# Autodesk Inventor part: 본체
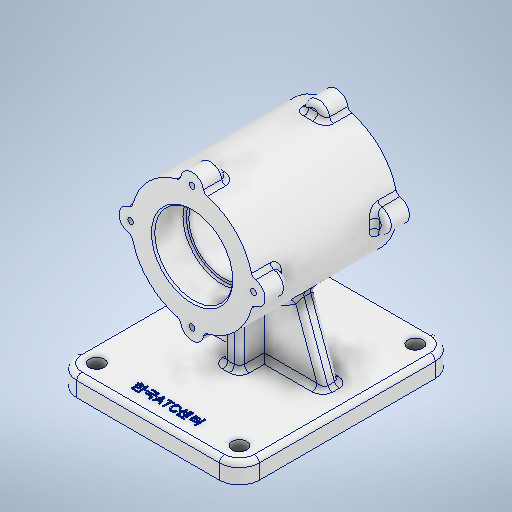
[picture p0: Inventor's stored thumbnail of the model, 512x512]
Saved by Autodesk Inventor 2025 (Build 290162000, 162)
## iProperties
Created: 2024-08
Part Number: 본체
Material: 알루미늄 6061
Document SubType Name: Modeling
Designer: Administrator
Density: 2.7 g/cm^3
Appearance: 알루미늄 - 평지
Mass: 1214.48 g
Surface Area: 799.178 cm^2
Volume: 449.808 cm^3
Author: Administrator
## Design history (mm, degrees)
sketch "스케치3"
  geometry: L1 (55, 70)-(-55, 70); L2 (-55, 70)-(-55, -60); L3 (-55, -60)-(55, -60); L4 (55, -60)-(55, 70); 1 further point
  constraints: 8 end point, 2 parallel, 1 horizontal, 1 perpendicular
  dimensions: "d7" = 70 distance from line of L1 point (0, 0); "d8" = 130 distance of L3.end L1.start; "d9" = 110 distance of L2.end L3.end; "d10" = 55 distance from line of L4 point (0, 0)
extrude "돌출2" new body sketch "스케치3" distance "d11" = 12; taper "d12" = 0 deg
sketch "스케치4"
  geometry: C1 r 37 at (0, 82); 1 further point
  constraints: 1 centre point, 1 vertical alignment
  dimensions: "d13" = 82 distance of point (0, 0) C1.centre; "d15" = 37 radius of C1
extrude "돌출3" join sketch "스케치4" stored distance "d16" = 87; taper "d17" = 0 deg
fillet "모깎기1" dims "d18" = 12
sketch "스케치5"
  geometry: L1 (43, 12)-(-43, 12) reference; L2 (-55, 12)-(-43, 12) reference; L3 (43, 12)-(55, 12) reference; L4 (41, 12)-(13.165, 88.475); L5 (-41, 12)-(-13.165, 88.475); L6 (-13.165, 88.475)-(13.165, 88.475); 2 further points
  constraints: 6 end point, 2 point on line, 1 equal length
  dimensions: "d20" = 14 distance of L3.end L4.start; "d21" = 110 deg angle of L3 L4; "d22" = 14 distance of L2.start L5.start; "d23" = 110 deg angle of L2 L5
extrude "돌출4" join sketch "스케치5" stored distance "d24" = 10; taper "d25" = 0 deg
sketch "스케치6"
  geometry: L1 (-5, -20)-(5, -20); L2 (5, -20)-(5, 20); L3 (5, 20)-(-5, 20); L4 (-5, 20)-(-5, -20); L5 (-5, -20)-(5, 20); L6 (5, -20)-(-5, 20); 1 further point
  constraints: 12 end point, 2 midpoint, 2 parallel, 1 horizontal, 1 perpendicular
  dimensions: "d26" = 40 distance of L3.end L1.start; "d27" = 10 distance of L2.end L3.end
extrude "돌출5" join sketch "스케치6" distance "d28" = 70; taper "d29" = 0 deg
sketch "스케치7"
  geometry: C1 r 37 at (0, 0) reference; 2 further points
  constraints: 1 coincident
hole "구멍1" sketch "스케치7" at (0, 0) diameter "d30" = 47; stored, may be unused: countersink angle "d34" = 90 deg, drill point angle "d36" = 0 deg; dims "d31" = 6, "d32" = 4, "d33" = 2, "d35" = 19
sketch "스케치8"
  geometry: C1 r 23.5 at (0, 0) reference; 2 further points
  constraints: 1 coincident
hole "구멍2" sketch "스케치8" at (0, 0) diameter "d37" = 42; stored, may be unused: countersink angle "d41" = 90 deg, drill point angle "d43" = 0 deg; dims "d38" = 6, "d39" = 4, "d40" = 2, "d42" = 1000
sketch "스케치9"
  geometry: C1 r 37 at (0, 0) reference; 2 further points
  constraints: 1 coincident
hole "구멍3" sketch "스케치9" at (0, 0) diameter "d44" = 47; stored, may be unused: countersink angle "d48" = 90 deg, drill point angle "d50" = 0 deg; dims "d45" = 6, "d46" = 4, "d47" = 2, "d49" = 19
fillet "모깎기2" dims "d51" = 1
chamfer "모따기1" distance "d52" = 1; stored, may be unused: second distance "d53" = 2, angle "d54" = 45 deg
chamfer "모따기2" distance "d55" = 1; stored, may be unused: second distance "d56" = 2, angle "d57" = 45 deg
fillet "모깎기3" dims "d58" = 3
fillet "모깎기4" dims "d59" = 3
sketch "스케치10"
  geometry: L1 (-43, -82)-(43, -82) reference; C1 r 7 at (0, 37); 3 further points
  constraints: 2 vertical alignment, 1 centre point, 1 midpoint, 1 other
  dimensions: "d61" = 7 radius of C1
extrude "돌출6" join sketch "스케치10" distance "d62" = 14; taper "d63" = 0 deg
fillet "모깎기5" dims "d64" = 3
fillet "모깎기6" dims "d65" = 3
sketch "스케치11"
  geometry: 1 further point
sketch "스케치12"
  geometry: 1 further point
sketch "스케치13"
  geometry: A1 r 7 centre (0, 119) between (6.889, 120.239) and (-6.889, 120.239) reference; 2 further points
  constraints: 1 coincident
hole "구멍4" sketch "스케치13" at (0, 119) diameter "d66" = 3.45873; stored, may be unused: countersink angle "d70" = 90 deg, drill point angle "d72" = 120 deg; dims "d67" = 8, "d68" = 4, "d69" = 2, "d71" = 10
fillet "모깎기7" dims "d76" = 3
fillet "모깎기8" dims "d77" = 3
sketch "스케치14"
  geometry: L1 (-43, -70)-(43, -70) reference; 2 further points
  dimensions: "d82" = 12 distance from line of L1 point (43, -58); "d83" = 43 horizontal distance of point (0, 0) point (43, -58)
hole "구멍5" sketch "스케치14" at (43, -58) diameter "d84" = 9; stored, may be unused: countersink angle "d88" = 90 deg, drill point angle "d90" = 0 deg; dims "d85" = 8, "d86" = 4, "d87" = 2, "d89" = 100
sketch "스케치15"
  geometry: L1 (-43, -70)-(43, -70) reference; L2 (43, 60)-(-43, 60) reference; 4 further points
  dimensions: "d91" = 12 distance from line of L1 point (-43, -58); "d92" = 43 horizontal distance of point (0, 0) point (-43, -58); "d93" = 12 distance from line of L2 point (-43, 48); "d94" = 43 horizontal distance of point (0, 0) point (-43, 48); "d95" = 43 horizontal distance of point (0, 0) point (43, 48); "d96" = 12 distance from line of L2 point (43, 48)
hole "구멍6" sketch "스케치15" at (-43, -58), (43, 48), (-43, 48) diameter "d97" = 9; stored, may be unused: countersink angle "d101" = 90 deg, drill point angle "d103" = 0 deg; dims "d98" = 6, "d99" = 4, "d100" = 2, "d102" = 100
sketch "스케치16"
  geometry: 3 further points
  constraints: 1 coincident, 1 vertical alignment, 1 other
  dimensions: "d104" = 58 distance of point (0, -58) point (0, 0)
feature "엠보싱1" sketch "스케치16" dims "d7" = 70, "d8" = 130, "d9" = 110, "d10" = 55, "d105" = 0.5, "d106" = 0
fillet "모깎기9" dims "d107" = 3
node "솔리드2"
pattern_circular "원형 패턴1" dims angle "d74" = 360 deg
mirror "미러1"
pattern_circular "원형 패턴2" dims angle "d79" = 360 deg
mirror "미러2"
feature "A9D066F2-1C7D-4E18-AEED-F7BC21143FA4" dims "d30" = 47, "d31" = 6, "d32" = 4, "d33" = 2, "d34" = 90 deg, "d35" = 19, "d36" = 0
